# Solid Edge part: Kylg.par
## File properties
Author: Georg
Template: Iso Part.par
Last saved by: Georg
Revision: 2
Application: Solid Edge
Accuracy: 0,990
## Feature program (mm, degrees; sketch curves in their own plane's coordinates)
sketch for "unnamed Protrusion 1" plane through (0, 0, 0) normal (1, 0, 0) x-axis (0, 1, 0)
  line (-36.9679, -25.2009) -> (-26.9679, -25.2009)
  line (-26.9679, -25.2009) -> (-26.9679, -19.2009)
  line (-26.9679, -19.2009) -> (-36.9679, -19.2009)
  line (-36.9679, -19.2009) -> (-36.9679, -25.2009)
  dimension (linear) = 26.9679
  dimension (linear) = 26.9679
extrude "unnamed Protrusion 1" add finite 90 along +normal
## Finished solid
Body 1: solid body, 6 faces, 12 edges, 8 vertices.
  Faces by surface: plane 6
  Edges by curve: line 12
Bounding box of the edges (mm): 90.000 x 10.000 x 6.000, from (0, -36.9679, -25.2009) to (90, -26.9679, -19.2009).
Planar faces by outward normal: +x 1, +y 1, +z 1, -x 1, -y 1, -z 1
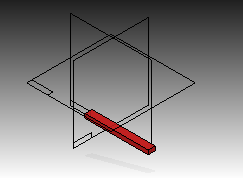
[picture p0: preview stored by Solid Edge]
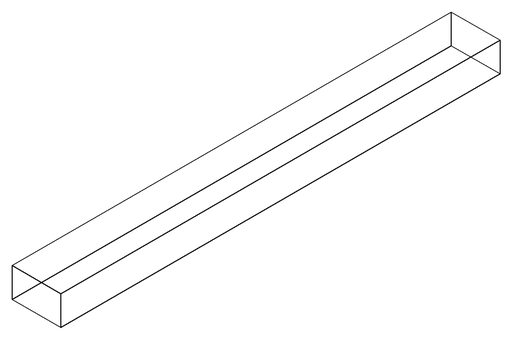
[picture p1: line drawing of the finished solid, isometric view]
